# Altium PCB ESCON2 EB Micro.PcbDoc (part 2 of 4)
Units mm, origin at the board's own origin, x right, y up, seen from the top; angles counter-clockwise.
Board outline 75.6 x 72 mm, 8 copper layers (Top Side, Mid Layer 1, Mid Layer 2, Mid Layer 3, Mid Layer 4, Mid Layer 5, Mid Layer 6, Bottom Side), stack 1.555 mm thick; 192 components, 85 nets, 547 pads, 2387 vias.
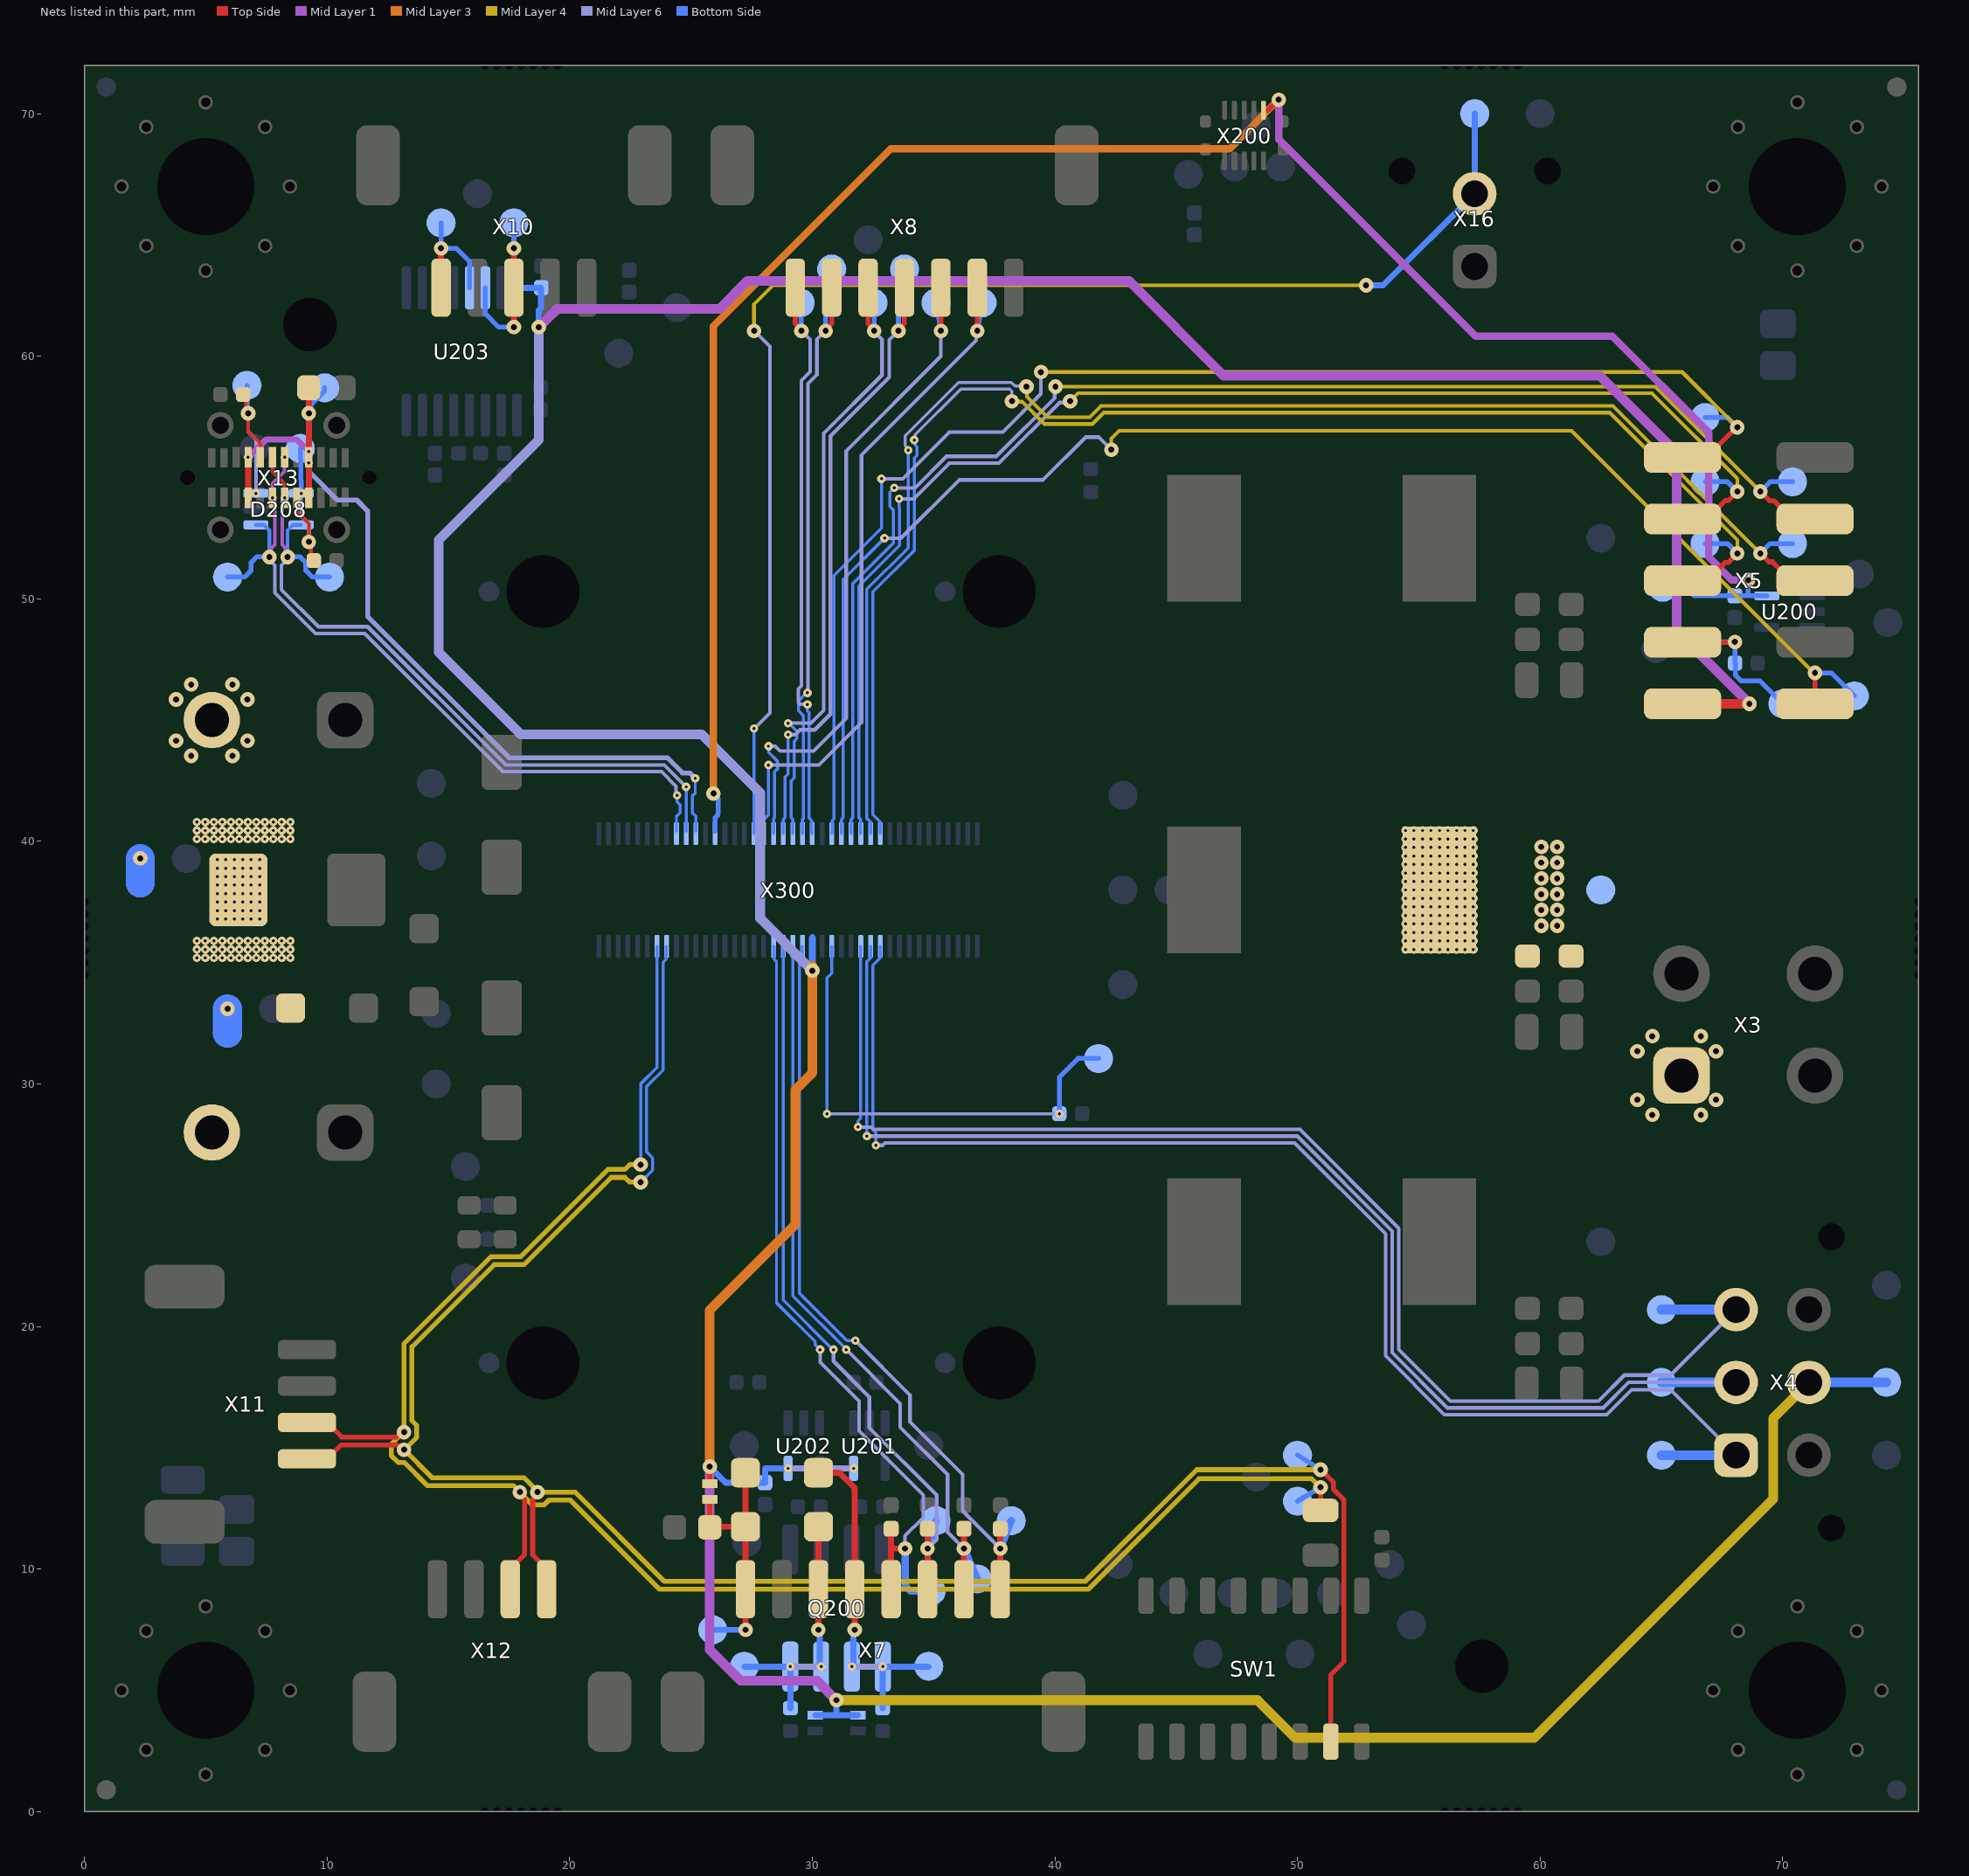
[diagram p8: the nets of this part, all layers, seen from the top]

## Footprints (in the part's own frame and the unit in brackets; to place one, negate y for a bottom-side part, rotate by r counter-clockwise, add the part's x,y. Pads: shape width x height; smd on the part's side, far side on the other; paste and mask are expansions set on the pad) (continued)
WURTH_9774040943_NPTH [mm] "WA-SMST SMT Steel Spacer with through hole Ø2.25mm, L=4mm"
  round 0 hole 3 unplated paste-2539.97 mask+1.25: 0(0,0)
  round 0.85 smd paste-5 mask+0.102: 1(2.225,0)
  Multi-Layer lines w0.85: 2.225,0 cw(c0,0) -2.225,0 cw(c0,0) 2.225,0
  body extent -2.17,-2.16 2.17,2.16, height 4

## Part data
C200 C201 C203 C207 C208 C209 C210 C211 C212: library part CMP-000709-3, "100nF X7R >=16V 20%", Case=0402, Case (Metric)=1005, Dielectric=X7R, Manufacturer=X, Max Operating Temperature=125°C, Maximum Working Voltage=16V, Min Operating Temperature=-55°C, Part Number="Ceramic, 0402, 100nF, 20%, >{}16V, X7R, @, Soft Termination: N, -55°C to 125°C", Tolerance=20%
C202 C206: library part CMP-000703-3, "100nF X7R >=100V 20%", Case=0603, Case (Metric)=1608, Dielectric=X7R, Manufacturer=X, Max Operating Temperature=125°C, Maximum Working Voltage=100V, Min Operating Temperature=-55°C, Part Number="Ceramic, 0603, 100nF, 20%, >{}100V, X7R, @, Soft Termination: N, -55°C to 125°C", Tolerance=20%
C204 C205: library part CMP-000937-4, "10nF X7R >=630V 20%", Case=0805, Case (Metric)=2012, Dielectric=X7R, Dielectric Withstanding Voltage="> 850V 1sec", Manufacturer=Murata, Max Operating Temperature=125°C, Maximum Working Voltage=630V, Min Operating Temperature=-55°C, Tolerance=20%
C300 C301 C302: library part CMP-000967-5, "Polymer Hybrid Elco 22uF >=80V 20% D=8mm, H=10.5mm", Case="G, D{}8mm, H{}10.5mm", Manufacturer=Panasonic, Max Operating Temperature=105°C, Maximum Working Voltage=80V, Min Operating Temperature=-55°C, Ripple Current=1.55A, Tolerance=20%
C303 C304 C305: library part CMP-001011-3, "470p C0G/NP0/X7R >=100V 20%", Case=0603, Case (Metric)=1608, Dielectric=C0G/NP0/X7R, Manufacturer=X, Max Operating Temperature=125°C, Maximum Working Voltage=100V, Min Operating Temperature=-55°C, Part Number="Ceramic, 0603, 470pF, 20%, >{}100V, C0G/NP0/X7R, @, Soft Termination: N, -55°C to 125°C", Tolerance=20%
C306 C307 C308: library part CMP-001012-4, "220pF C0G/NP0/X7R >=100V 20%", Case=0603, Case (Metric)=1608, Dielectric=C0G/NP0/X7R, Manufacturer=X, Max Operating Temperature=125°C, Maximum Working Voltage=100V, Min Operating Temperature=-55°C, Part Number="Ceramic, 0603, 220pF, 20%, >{}100V, C0G/NP0/X7R, @, Soft Termination: N, -55°C to 125°C", Tolerance=20%
D200: library part CMP-001106-5, "Transient Voltage Suppressor Diode, 12V V(RWM), Bidirectional, 100W, 1 Element, SOD-882/DFN1006", Breakdown Voltage=13V, Case="SOD-882; DFN1006", Manufacturer=Diodes, Max Operating Temperature=125°C, Min Operating Temperature=-40°C
D201 D204 D205: library part CMP-000606-13, "Diode Switching, >=70V, >=150mA, SOD882/DFN1006/0402/SOD-923F", Case="SOD882 / DFN1006 / 0402 / SOD-923F", Manufacturer=MCC, Max Operating Temperature=125°C, Min Operating Temperature=-40°C, Reverse Voltage=70V, RMS Current=150mA
D202 D203 D209 D210: library part CMP-000066-17, "Transient Voltage Suppressor Diode, 30V V(RWM), Bidirectional, ESD, 1 Element, 0402", Breakdown Voltage=30V, Case=0402, Manufacturer=Panasonic, Max Operating Temperature=125°C, Min Operating Temperature=-55°C
D206 D207 D300 D301: library part CMP-000633-9, "Schottky Diode, >=90V, >=1A, SOD-123FL/SOD-123W", Case="Sub SMA; SOD-123FL", Manufacturer="Taiwan Semiconductor", Max Operating Temperature=150°C, Min Operating Temperature=-55°C, Reverse Voltage=90V, RMS Current=1A
D208: library part CMP-000635-10, "Transient Voltage Suppressor Diode, 4-Line, 5V V(RWM), Unidirectional, 30W, 4 Element , SOT353/SC-88A", Breakdown Voltage=6.8V, Case="SOT353; SC-88A; SOT323-5L", Clamping Voltage=12V, Manufacturer=Nexperia, Max Breakdown Voltage=7.14V, Max Junction Temperature=150°C, Min Breakdown Voltage=6.46V, Min Operating Temperature=-65°C
D302 D303: library part CMP-001103-4, "Transient Voltage Suppressor Diode, 60V V(RWM), Unidirectional, 400W, 1 Element, DO-214AC", Breakdown Voltage=66.7V, Case=DO-214AC, Clamping Voltage=96.8V, Manufacturer=X, Max Operating Temperature=150°C, Min Operating Temperature=-55°C
DS200: library part CMP-000723-6, "Single Color Chip LED, red, 0603", Case=0603, Color(s)=Red, Manufacturer=Dialight, Max Operating Temperature=100°C, Min Operating Temperature=-40°C
DS201: library part CMP-000722-5, "Single Color Chip LED, green, 0603", Case=0603, Color(s)=Green, Manufacturer=Dialight, Max Operating Temperature=100°C, Min Operating Temperature=-40°C
F300: library part CMP-001757-3, "Electric Fuse, Very Fast Blow, 10A, 125VAC, 125VDC, 35A (IR), Clip Assembly", Case="0157 with Fuse Clip", Current Rating=10A, Manufacturer=Littelfuse, Max Operating Temperature=125°C, Maximum Working Voltage=125V, Min Operating Temperature=-55°C
FD200 FD201 FD202 FD203: library part CMP-000010-5, "Fiducial, Global, Round; 0.80 mm D, 1.60 mm Clearance"
L300 L301 L302: library part CMP-001747-7, "Inductor Shielded, 15uH, 20%, I_RMS>6.5A, I_Sat>9.8A, R<26mOhm, 12.0x12.0mm, Height<=10mm", Case=0, Max Operating Temperature=125°C, Min Operating Temperature=-40°C, RMS Current=5.7A, Saturation Current=9.8A, Tolerance=20%
LS200: library part CMP-001088-3, "Layer Stair 8 Layer"
MH200 MH201 MH202 MH203: library part CMP-001801-1, "Mounting Hole, Non-Plated; 9.00 mm Clearance, 4.00 mm Hole (with 8 vias), for 4mm Dia. Snap-In Spacer"
MH204 MH205: library part CMP-001004-5, "Mounting Hole, Non-Plated; 0.00 mm Clearance, 2.20 mm Hole"
MP200 MP201 MP202 MP203: library part CMP-001759-4, "WA-SNTI Plastic Spacer Stud, D=4.0mm, L=10mm, M3, SW=6", Max Operating Temperature=110°C, Min Operating Temperature=-30°C
MP300 MP301: library part CMP-001744-2, "WA-SMST SMT Steel Spacer with through hole Ø 2.25mm, L=4mm", Manufacturer=Wurth, Max Operating Temperature=150°C, Min Operating Temperature=-55°C
MP302 MP303: library part CMP-001745-2, "WA-SMST SMT Steel Spacer with internal Thread M2, L=4mm", Manufacturer=Wurth, Max Operating Temperature=150°C, Min Operating Temperature=-55°C
Q200: library part CMP-001108-5, "N-Channel MOSFET, Self Protected, 36V, 0.5ohm, SO-8", Case="SO-8, SOIC-8, PG-DSO-8", Drain Source Voltage=36V, Manufacturer="ST Microelectronics", Max Operating Temperature=150°C, Min Operating Temperature=-55°C
R200: library part CMP-000161-11, "47R 1% 62.5mW 100ppm", Case=0402, Case (Metric)=1050, Manufacturer=X, Max Junction Temperature=155°C, Maximum Overload Voltage=100V, Maximum Working Voltage=50V, Min Operating Temperature=-55°C, Part Number="Thick-Film, 0402, 47, 1%, 62.5mW@70°C, 50V, 100ppm, -55°C to 155°C", Power Rating=62.5mW, Power Rating Temperature=70°C, Temperature Coefficient=100ppm, Tolerance=1%
R202 R203: library part CMP-000197-11, "2.2k 1% 62.5mW 100ppm", Case=0402, Case (Metric)=1050, Manufacturer=X, Max Junction Temperature=155°C, Maximum Overload Voltage=100V, Maximum Working Voltage=50V, Min Operating Temperature=-55°C, Part Number="Thick-Film, 0402, 2.2k, 1%, 62.5mW@70°C, 50V, 100ppm, -55°C to 155°C", Power Rating=62.5mW, Power Rating Temperature=70°C, Temperature Coefficient=100ppm, Tolerance=1%
R204 R205: library part CMP-000173-11, "220R 1% 62.5mW 100ppm", Case=0402, Case (Metric)=1050, Manufacturer=X, Max Junction Temperature=155°C, Maximum Overload Voltage=100V, Maximum Working Voltage=50V, Min Operating Temperature=-55°C, Part Number="Thick-Film, 0402, 220, 1%, 62.5mW@70°C, 50V, 100ppm, -55°C to 155°C", Power Rating=62.5mW, Power Rating Temperature=70°C, Temperature Coefficient=100ppm, Tolerance=1%
R206: library part CMP-000935-4, "2M 5% 250mW 200ppm >=500V", Case=1206, Case (Metric)=3216, Manufacturer=X, Max Junction Temperature=155°C, Maximum Overload Voltage=1kV, Maximum Working Voltage=500V, Min Operating Temperature=-55°C, Part Number="Thick-Film, 1206, 2M, 5%, 250mW@70°C, 500V, 200ppm, -55°C to 155°C", Power Rating=250mW, Power Rating Temperature=70°C, Temperature Coefficient=200ppm, Tolerance=5%
R207 R208: library part CMP-000206-11, "5.1k 1% 62.5mW 100ppm", Case=0402, Case (Metric)=1050, Manufacturer=X, Max Junction Temperature=155°C, Maximum Overload Voltage=100V, Maximum Working Voltage=50V, Min Operating Temperature=-55°C, Part Number="Thick-Film, 0402, 5.1k, 1%, 62.5mW@70°C, 50V, 100ppm, -55°C to 155°C", Power Rating=62.5mW, Power Rating Temperature=70°C, Temperature Coefficient=100ppm, Tolerance=1%
R209: library part CMP-000325-10, "120R 1% 125mW 100ppm", Case=0805, Case (Metric)=2012, Manufacturer=X, Max Junction Temperature=155°C, Maximum Overload Voltage=300V, Maximum Working Voltage=150V, Min Operating Temperature=-55°C, Part Number="Thick-Film, 0805, 120, 1%, 125mW@70°C, 150V, 100ppm, -55°C to 155°C", Power Rating=125mW, Power Rating Temperature=70°C, Temperature Coefficient=100ppm, Tolerance=1%
R210: library part CMP-000466-10, "0R Jumper", Case=0402, Case (Metric)=1050, Manufacturer=X, Max Junction Temperature=155°C, Maximum Overload Voltage=100V, Maximum Working Voltage=50V, Min Operating Temperature=-55°C, Part Number="Thick-Film, 0402, 0, -55°C to 155°C", RMS Current=1A
R211 R212: library part CMP-000185-11, "680R 1% 62.5mW 100ppm", Case=0402, Case (Metric)=1050, Manufacturer=X, Max Junction Temperature=155°C, Maximum Overload Voltage=100V, Maximum Working Voltage=50V, Min Operating Temperature=-55°C, Part Number="Thick-Film, 0402, 680, 1%, 62.5mW@70°C, 50V, 100ppm, -55°C to 155°C", Power Rating=62.5mW, Power Rating Temperature=70°C, Temperature Coefficient=100ppm, Tolerance=1%
R213 R214 R215 R324: library part CMP-000492-11, "10k 1% 62.5mW 100ppm", Case=0402, Case (Metric)=1050, Manufacturer=X, Max Junction Temperature=155°C, Maximum Overload Voltage=100V, Maximum Working Voltage=50V, Min Operating Temperature=-55°C, Part Number="Thick-Film, 0402, 10k, 1%, 62.5mW@70°C, 50V, 100ppm, -55°C to 155°C", Power Rating=62.5mW, Power Rating Temperature=70°C, Temperature Coefficient=100ppm, Tolerance=1%
R309 R310 R311: library part CMP-001764-2, "270R 1% 250mW 100ppm", Case=0805, Case (Metric)=2012, Max Junction Temperature=155°C, Maximum Overload Voltage=300V, Maximum Working Voltage=150V, Min Operating Temperature=-55°C, Part Number="Thick-Film, 0805, 270, 1%, 250mW@70°C, 150V, 100ppm, -55°C to 155°C", Power Rating=250mW, Power Rating Temperature=70°C, Temperature Coefficient=100ppm, Tolerance=1%
STEG200 STEG201 STEG202 STEG203 STEG204 STEG205: library part CMP-000007-5, "Breakaway tabs; 4.00 mm L X 0.90 mm W, 7 Hole"
SW1: library part CMP-001031-3, "Slide Dip Switch, 8 Switches, 0.025A, 24VDC, SMD", Manufacturer=Diptronics, Max Operating Temperature=85°C, Min Operating Temperature=-40°C
SYM200: library part CMP-001233-2, "Barcode EMS; 5.0 x 5.0 mm"
SYM201 SYM202: library part CMP-000018-5, "ESD-Sign; 5.0 mm L X 4.5 mm W"
SYM203: library part CMP-001854-7, "PCB Marking; 12.0 x 6.0 mm"
TP200 TP201 TP202 TP203 TP204 TP205 TP206 TP207 TP208 TP209 TP211 TP212 TP213 TP214 TP215 TP216 TP217 TP218 TP219 TP220 TP221 TP222 TP223 TP224 TP225 TP226 TP227 TP228 TP229 TP230 TP231 TP232 TP233 TP234 TP235 TP236 TP237 TP238 TP239 TP240 TP241 TP242 TP243 TP244 TP245 TP246 TP247 TP248 TP249 TP250 TP251 TP252 TP253 TP254 TP255 TP256 TP257 TP258 TP259 TP260 TP261 TP262 TP263 TP264 TP265 TP266 TP267 TP268 TP269 TP270 TP271 TP272 TP300 TP301 TP302 TP304 TP309 TP313 TP314 TP315 TP316: library part CMP-000014-7, "Test Point; 1 pin, 1.20 mm D"
U200: library part CMP-001041-6, "Single buffer with Schmitt-Trigger inputs", Case="5-TSSOP, SC-70-5, SOT-353", Manufacturer="Texas Instruments", Max Operating Temperature=125°C, Max Storage Temperature=150°C, Max Supply Voltage=5.5V, Min Operating Temperature=-40°C, Min Storage Temperature=-65°C, Min Supply Voltage=1.65V
U201 U202: library part CMP-002037-1, "Single, 2-Input NAND Gate, 5V", Case="SC-88A , SC-70-5, SOT353-1", Max Operating Temperature=125°C, Max Supply Voltage=5.5V, Min Operating Temperature=-40°C, Min Supply Voltage=4.5V
U203: library part CMP-000646-4, "RS-232 Line Transceiver, Dual channel 120kbps , 5.0V, TSSOP16", Case=TSSOP16, Manufacturer="Texas instruments", Max Operating Temperature=85°C, Max Supply Voltage=5.5V, Min Operating Temperature=-40°C, Min Supply Voltage=4.5V
X1 X2: library part CMP-001018-6, "Mini-Fit Jr. Vertical Header, 4.20mm Pitch, Dual Row, 2 Circuits, without Snap-in Plastic Peg PCB Lock, Tin, Natural", Max Operating Temperature=105°C, Min Operating Temperature=-40°C, Operating Current=9A, Operating Voltage=600V
X3: library part CMP-001016-8, "Mini-Fit Jr. Vertical Header, 4.20mm Pitch, Dual Row, 4 Circuits, without Snap-in Plastic Peg PCB Lock, Tin, Natural", Max Operating Temperature=105°C, Min Operating Temperature=-40°C, Operating Current=9A, Operating Voltage=600V
X4: library part CMP-001098-6, "Micro-Fit 3.0 Vertical Header, 3.00mm Pitch, Dual Row, 6 Circuits, with PCB Polarizing Peg, Black", Manufacturer=Molex, Max Operating Temperature=105°C, Min Operating Temperature=-40°C, Operating Current=8.5A, Operating Voltage=600V
X5: library part CMP-001165-3, "Header, 2.54mm Pitch, Dual Row, SMT, Vertical, 10 Circuits", Manufacturer=Amphenol, Max Operating Temperature=125°C, Min Operating Temperature=-65°C, Operating Current=3A, Operating Voltage=500V
X7: library part CMP-001014-7, "1.50mm Pitch, CLIK-Mate PCB Receptacle, Single Row, Surface Mount, Tin Plating, Positive Lock, with Pick-and-Place Polyimide Tape, 8 Circuits, Beige", Manufacturer=Molex, Max Operating Temperature=105°C, Min Operating Temperature=-40°C, Operating Current=2A, Operating Voltage=100V
X8: library part CMP-001015-7, "1.50mm Pitch, CLIK-Mate PCB Receptacle, Single Row, Surface Mount, Tin Plating, Positive Lock, with Pick-and-Place Polyimide Tape, 7 Circuits, Beige", Manufacturer=Molex, Max Operating Temperature=105°C, Min Operating Temperature=-40°C, Operating Current=2A, Operating Voltage=100V
X10: library part CMP-001023-6, "1.50mm Pitch, CLIK-Mate PCB Receptacle, Single Row, Surface Mount, Tin Plating, Positive Lock, with Pick-and-Place Polyimide Tape, 5 Circuits, Beige", Manufacturer=Molex, Max Operating Temperature=105°C, Min Operating Temperature=-40°C, Operating Current=2A, Operating Voltage=100V
X11 X12: library part CMP-001170-6, "1.50mm Pitch, CLIK-Mate PCB Receptacle, Single Row, Surface Mount, Tin Plating, Positive Lock, with Pick-and-Place Polyimide Tape, 4 Circuits, Beige", Manufacturer=Molex, Max Operating Temperature=105°C, Min Operating Temperature=-40°C, Operating Current=2A, Operating Voltage=100V
X13: library part CMP-001110-9, "USB Type C, SHLD, 24poles, vertical", Manufacturer=GTC, Max Operating Temperature=85°C, Min Operating Temperature=-25°C
X16: library part CMP-001107-4, "Micro-Fit 3.0 Vertical Header, 3.00mm Pitch, Dual Row, 2 Circuits, with PCB Polarizing Peg, Black", Manufacturer=Molex, Max Operating Temperature=105°C, Min Operating Temperature=-40°C, Operating Current=8.5A, Operating Voltage=600V
X200: library part CMP-001083-11, "Board to Board Connector, 2*5 pole, SMD, 0.4mm pitch, 1.5mm stacking Height", Manufacturer=Panasonic, Max Operating Temperature=85°C, Min Operating Temperature=-55°C, Operating Current=300mA, Operating Voltage=60V
X300: library part CMP-001746-7, "SS4 0.40 mm Micro Blade & Beam Ultra Fine Pitch Socket, 80 poles", Manufacturer=Samtec, Max Operating Temperature=125°C, Min Operating Temperature=-55°C, Operating Current=1.6A, Operating Voltage=155V

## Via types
v1: diameter 0.35, hole 0.125, Top Side to Mid Layer 1, tented both sides, 1630 vias
v2: diameter 0.6, hole 0.25, Top Side to Bottom Side, 412 vias
v3: diameter 0.35, hole 0.125, Mid Layer 6 to Bottom Side, tented both sides, 345 vias

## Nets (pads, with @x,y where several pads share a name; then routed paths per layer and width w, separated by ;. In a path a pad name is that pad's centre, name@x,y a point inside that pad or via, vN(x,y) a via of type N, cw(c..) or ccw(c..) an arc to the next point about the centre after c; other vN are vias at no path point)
3V3: C200.2 TP202.1 U200.5 X200.1 X300.56 | length 85.5
  Top Side w0.2: X200.1@48.6,70.145 48.795,70.145 v2(49.225,70.575)
  Mid Layer 1 w0.3: v2(49.225,70.575) 49.225,68.95 57.35,60.825 62.975,60.825 66.95,56.85 66.95,51.725 67.9,50.775 v2(68.575,50.775)
  Mid Layer 3 w0.3: v2(25.925,41.975) 25.925,61.25 33.225,68.55 47.2,68.55 v2(49.225,70.575)
  Bottom Side w0.2: v2(25.925,41.975) 26.125,41.775 26.125,41.15 26.1,41.125 26.1,41.075 26,40.975 X300.56@26,40.425 ; TP202.1@65.05,50.475 66,50.475 66.35,50.125 C200.2@68.025,50.125 68.568,50.125 ; v2(68.575,50.775) 68.575,50.132 68.568,50.125 ; U200.5@69.34,50.125 68.568,50.125
5V0_sensor1_2: C201.2 C207.1 D201.2 D204.2 D205.2 TP223.1 U201.5 U202.5 U203.16 X4.5 X5.2 X300.35 | length 205.9
  Top Side w0.25: D201.2@25.775,13.525 v2(25.775,14.225)
  Top Side w0.4: X5.2@65.87,45.67 68.62,45.67 v2(68.625,45.675)
  Mid Layer 1 w0.4: v2(18.725,61.2) 19.475,61.95 26.175,61.95 27.325,63.1 43.05,63.1 46.95,59.2 62.45,59.2 65.625,56.025 65.625,48.675 v2(68.625,45.675) ; v2(25.775,14.225) 25.775,6.675 27.05,5.4 30.2,5.4 v2(31,4.6)
  Mid Layer 3 w0.4: v2(25.775,14.225) 25.775,20.675 29.3,24.2 29.3,29.75 30,30.45 v2(30,34.675) v2@30,34.875
  Mid Layer 6 w0.25: v3(29,14.155) v3(31.7,14.155)
  Mid Layer 6 w0.4: v2(18.725,61.2) 18.725,56.55 14.6,52.425 14.6,47.8 17.99,44.41 25.44,44.41 27.85,42 27.85,36.825 v2(30,34.675)
  Mid Layer 4 w0.4: v2(31,4.6) 48.35,4.6 49.9,3.05 59.75,3.05 69.6,12.9 69.6,16.225 X4.5@71.075,17.7
  Bottom Side w0.25: U203.16@17.825,62.825 C207.1@18.825,62.825 18.825,62 18.725,61.9 v2(18.725,61.2) ; v2(25.775,14.225) 26.435,13.565 C201.2@28.05,13.565 28.05,14.155 v3(29,14.155) ; D205.2@30.125,3.975 31,3.975 ; v2@31,4.75 v2(31,4.6) 31,3.975 ; D204.2@31.875,3.975 31,3.975
  Bottom Side w0.3: v2(30,34.675) X300.35@30,35.675 X300.35@30,36.025
  Bottom Side w0.4: X4.5@71.075,17.7 TP223.1@74.275,17.7
ADC_CB_Ident: R324.2 TP309.1 X300.31 | length 20
  Mid Layer 6 w0.125: v3(30.6,28.775) v3(40.18,28.775)
  Bottom Side w0.125: v3(30.6,28.775) 30.6,34.375 30.8,34.575 X300.31@30.8,35.675
  Bottom Side w0.2: v3(40.18,28.775) 40.18,30.28 40.95,31.05 TP309.1@41.8,31.05
C_AnIN1+: TP230.1 X8.1 X300.36 | length 24.5
  Top Side w0.2: X8.1@29.3,62.825 29.3,61.352 29.55,61.102 v2(29.55,61.05)
  Mid Layer 6 w0.15: v2(29.55,61.05) 29.91,60.69 29.91,59.356 29.55,58.996 29.55,46.405 29.425,46.28 29.425,45.738 29.513,45.65 v3(29.8,45.65)
  Bottom Side w0.125: v3(29.8,45.65) 29.8,45.379 29.875,45.304 29.875,40.961 29.975,40.861 29.975,40.35 X300.36@30,40.325
  Bottom Side w0.2: TP230.1@29.5,62.2 29.55,62.15 v2(29.55,61.05)
C_AnIN1-: TP231.1 X8.2 X300.38 | length 25.8
  Top Side w0.2: v2@30.55,61.102 30.8,61.352 X8.2@30.8,62.825
  Mid Layer 6 w0.15: v3(29.8,46.125) 29.825,46.15 29.825,58.875 30.189,59.239 30.189,60.689 v2(30.55,61.05)
  Bottom Side w0.125: X300.38@29.6,40.325 29.6,40.925 29.625,40.95 29.625,45.2 29.438,45.388 29.438,45.8 29.762,46.125 v3(29.8,46.125)
  Bottom Side w0.2: v2(30.55,61.05) 30.55,62 30.8,62.25 TP231.1@30.8,63.6
C_AnIN2+: TP232.1 X8.3 X300.40 | length 26.4
  Top Side w0.2: X8.3@32.3,62.825 32.3,61.352 32.55,61.102 v2(32.55,61.05)
  Mid Layer 6 w0.15: v3(29,44.875) 29.95,44.875 30.475,45.4 30.475,56.825 32.875,59.225 32.875,60.687 32.55,61.012 v2(32.55,61.05)
  Bottom Side w0.125: v3(29,44.875) 29.038,44.875 29.363,44.55 29.363,44.238 29.25,44.125 29.25,42.625 29.125,42.5 29.125,40.975 29.2,40.9 X300.40@29.2,40.325
  Bottom Side w0.2: TP232.1@32.5,62.2 32.55,62.15 v2(32.55,61.05)
C_AnIN2-: TP233.1 X8.4 X300.42 | length 27.7
  Top Side w0.2: v2@33.55,61.102 33.8,61.352 X8.4@33.8,62.825
  Mid Layer 6 w0.15: v3(29,44.4) 29.3,44.4 29.5,44.6 30.1,44.6 30.75,45.25 30.75,56.711 33.175,59.136 33.175,60.675 v2(33.55,61.05)
  Bottom Side w0.125: X300.42@28.8,40.325 28.8,40.9 28.875,40.975 28.875,42.65 29,42.775 v3(29,44.4)
  Bottom Side w0.2: v2(33.55,61.05) 33.55,62 33.8,62.25 TP233.1@33.8,63.6
C_AnOUT1: TP234.1 X8.5 X300.44 | length 28.2
  Top Side w0.2: v2(35.3,61.05) X8.5@35.3,62.825
  Mid Layer 6 w0.15: v3(28.2,43.925) 28.475,43.925 28.675,43.725 30.05,43.725 31.4,45.075 31.4,56.1 35.3,60 v2(35.3,61.05)
  Bottom Side w0.125: v3(28.2,43.925) 28.206,43.919 28.206,43.669 28.563,43.313 28.563,42.988 28.45,42.875 28.45,40.975 28.4,40.925 X300.44@28.4,40.325
  Bottom Side w0.2: TP234.1@35.1,62.2 v2(35.3,61.05)
C_AnOUT2: TP237.1 X8.6 X300.46 | length 28.5
  Top Side w0.2: v2(36.8,61.05) X8.6@36.8,62.825
  Mid Layer 6 w0.15: v3(28.2,43.15) 30.275,43.15 32.025,44.9 32.025,55.925 36.754,60.654 36.754,61.004 v2(36.8,61.05)
  Bottom Side w0.125: X300.46@28,40.325 28,40.9 28.2,41.1 v3(28.2,43.15)
  Bottom Side w0.2: v2(36.8,61.05) TP237.1@37,62.2
C_CANH: SW1.7 TP240.1 X11.1 X12.1 X300.65 | length 90.9
  Top Side w0.2: X11.1@9.175,14.55 10.015,14.55 10.59,15.125 12.867,15.125 13.067,14.925 v2(13.175,14.925) ; v2(18.675,13.175) 18.675,13.067 18.475,12.867 18.475,10.59 19.05,10.015 X12.1@19.05,9.175 ; v2(50.95,14.1) 50.967,14.1 51.475,13.592 51.475,13.3 51.917,12.858 51.917,6.192 51.375,5.65 SW1.7@51.375,2.893
  Mid Layer 4 w0.2: v2@22.937,25.962 22.463,25.962 22.275,26.15 21.71,26.15 18.11,22.55 16.885,22.55 13.5,19.165 13.5,16.125 13.7,15.925 13.7,15.433 13.192,14.925 v2(13.175,14.925) 14.325,13.775 18.111,13.775 18.675,13.211 v2(18.675,13.175) 20.225,13.175 23.9,9.5 41.25,9.5 45.85,14.1 v2(50.95,14.1)
  Bottom Side w0.125: v2(22.925,25.95) 23.425,26.45 23.425,26.955 23.175,27.205 23.175,29.9 23.85,30.575 23.85,35.014 23.975,35.139 23.975,35.65 X300.65@24,35.675
  Bottom Side w0.2: TP240.1@50,14.7 v2(50.95,14.1)
C_CANL: R209.2 TP241.1 X11.2 X12.2 X300.67 | length 80.4
  Top Side w0.2: X11.2@9.175,16.025 10.025,16.025 10.6,15.45 12.867,15.45 13.067,15.65 v2(13.175,15.65) ; X12.2@17.575,9.175 17.575,10.025 18.15,10.6 18.15,12.867 17.95,13.067 v2(17.95,13.175) ; R209.2@50.95,12.425 v2(50.95,13.375)
  Mid Layer 4 w0.2: v2(22.925,26.675) 22.475,26.675 22.275,26.475 21.575,26.475 17.975,22.875 16.75,22.875 13.175,19.3 v2(13.175,15.65) 13.146,15.65 12.643,15.147 12.643,14.686 12.93,14.4 13.175,14.4 14.125,13.45 17.675,13.45 v2(17.95,13.175) 17.95,13.158 18.458,12.65 18.95,12.65 19.15,12.85 20.025,12.85 23.7,9.175 41.385,9.175 45.935,13.725 50.583,13.725 50.933,13.375 v2(50.95,13.375)
  Bottom Side w0.125: v2(22.925,26.675) 22.925,30.004 23.6,30.679 X300.67@23.6,35.675
  Bottom Side w0.2: TP241.1@50,12.8 v2(50.95,13.375)
C_DigIN1: D203.2 TP269.1 X7.1 X300.37 | length 32.2
  Top Side w0.25: X7.1@37.75,9.175 D203.2@37.75,11.665
  Mid Layer 6 w0.15: v3(31.775,19.425) 34.025,17.175 34.025,16.075 36.2,13.9 36.2,12.4 v2(37.75,10.85)
  Bottom Side w0.125: X300.37@29.6,35.675 29.575,35.65 29.575,35.139 29.475,35.039 29.475,21.375 31.425,19.425 v3(31.775,19.425)
  Bottom Side w0.3: v2(37.75,10.85) TP269.1@38.2,12
C_DigIN2: D202.2 TP270.1 X7.2 X300.39 | length 31.6
  Top Side w0.25: X7.2@36.25,9.175 D202.2@36.25,11.665
  Mid Layer 6 w0.15: v3(31.4,19.05) 33.625,16.825 33.625,15.85 35.575,13.9 35.575,11.525 v2(36.25,10.85)
  Bottom Side w0.125: X300.39@29.2,35.675 29.2,21.261 v3@31.406,19.056
  Bottom Side w0.3: v2(36.25,10.85) TP270.1@36.8,9.6
C_DigIN3: D210.2 TP271.1 X7.3 X300.41 | length 31.3
  Top Side w0.25: X7.3@34.75,9.175 v2(34.75,10.85) D210.2@34.75,11.665
  Mid Layer 6 w0.15: v3(30.875,19.05) 30.875,18.575 32.35,17.1 32.35,15.825 35.125,13.05 35.125,11.225 v2(34.75,10.85)
  Bottom Side w0.125: X300.41@28.8,35.675 28.8,21.095 v3@30.86,19.035
  Bottom Side w0.3: v2(34.75,10.85) TP271.1@35.1,12
C_DigIN4: D209.2 TP272.1 X7.4 X300.43 | length 33.5
  Top Side w0.25: X7.4@33.25,9.175 33.25,10.85 ; D209.2@33.25,11.665 33.25,10.85 ; v2(33.825,10.85) 33.25,10.85
  Mid Layer 6 w0.15: v3(30.325,19.05) 30.325,18.525 31.925,16.925 31.925,15.7 34.575,13.05 34.575,12.125 33.825,11.375 v2(33.825,10.85)
  Bottom Side w0.125: X300.43@28.4,35.675 28.425,35.65 28.425,35.139 28.525,35.039 28.525,20.982 30.125,19.382 30.125,19.25 v3(30.325,19.05)
  Bottom Side w0.3: v2(33.825,10.85) 33.825,9.325 34.05,9.1 TP272.1@34.9,9.1
C_DigOUT1: D206.2 Q200.5 Q200.6 R202.1 TP224.1 X7.5 | length 14
  Top Side w0.25: D206.2@30.255,13.975 31.125,13.975 31.75,13.35 X7.5@31.75,9.175 v2(31.75,7.5)
  Mid Layer 6 w0.25: v3(31.635,5.98) v3(32.905,5.98)
  Bottom Side w0.25: v3(31.635,5.98) 31.693,6.038 31.693,7.443 v2(31.75,7.5) ; R202.1@32.9,4.27 Q200.5@32.9,5.98 ; v3(32.905,5.98) TP224.1@34.8,5.98
C_DigOUT2: D207.2 Q200.7 Q200.8 R203.1 TP225.1 X7.6 | length 10.7
  Top Side w0.25: v2(30.25,7.5) X7.6@30.25,9.175 ; X7.6@30.255,9.175 D207.2@30.255,11.75
  Mid Layer 6 w0.25: v3(29.095,5.98) v3(30.365,5.98)
  Bottom Side w0.25: TP225.1@27.2,5.98 v3(29.095,5.98) ; R203.1@29.1,4.27 Q200.8@29.1,5.975 ; v2(30.25,7.5) 30.308,7.443 30.308,6.038 v3(30.365,5.98)
C_MotorTemp: TP260.1 X16.2 X300.48 | length 57.2
  Mid Layer 6 w0.15: v3(27.6,44.65) 28.25,45.3 28.25,60.4 v2(27.6,61.05)
  Mid Layer 4 w0.15: v2(27.6,61.05) 27.6,62.15 28.375,62.925 v2(52.825,62.925)
  Bottom Side w0.125: X300.48@27.6,40.325 v3(27.6,44.65)
  Bottom Side w0.25: v2(52.825,62.925) 53.525,62.925 X16.2@57.3,66.7 TP260.1@57.3,70
C_S1_Hall1: TP266.1 X4.1 X300.21 | length 56.1
  Mid Layer 6 w0.15: v3(32.625,27.475) 32.9,27.475 33,27.575 49.875,27.575 53.625,23.825 53.625,18.8 56.05,16.375 62.75,16.375 63.775,17.4 65.375,17.4 X4.1@68.075,14.7
  Bottom Side w0.125: v3(32.625,27.475) 32.625,28 32.5,28.125 32.5,34.9 32.8,35.2 X300.21@32.8,35.675
  Bottom Side w0.4: TP266.1@65,14.7 X4.1@68.075,14.7
C_S1_Hall2: TP267.1 X4.2 X300.23 | length 54.8
  Mid Layer 6 w0.15: v3(32.25,27.85) 49.989,27.85 53.9,23.939 53.9,18.925 56.175,16.65 62.6,16.65 63.65,17.7 X4.2@68.075,17.7
  Bottom Side w0.125: v3(32.25,27.85) 32.25,35.047 32.4,35.197 X300.23@32.4,35.675
  Bottom Side w0.4: TP267.1@65,17.7 X4.2@68.075,17.7
C_S1_Hall3: TP268.1 X4.3 X300.25 | length 55.9
  Mid Layer 6 w0.15: v3(31.888,28.225) 32.425,28.225 32.525,28.125 50.103,28.125 54.175,24.053 54.175,19.05 56.3,16.925 62.4,16.925 63.475,18 65.375,18 X4.3@68.075,20.7
  Bottom Side w0.125: v3(31.888,28.225) 31.888,28.488 32,28.6 X300.25@32,35.675
  Bottom Side w0.4: TP268.1@65,20.7 X4.3@68.075,20.7
C_S2_/A: TP216.1 X5.5 X300.24 | length 61.1
  Top Side w0.2: v2(69.075,51.875) 69.425,51.525 69.575,51.525 70.35,50.75 X5.5@71.33,50.75
  Mid Layer 6 w0.125: v3(33.95,56.125) 33.95,56.186 33.828,56.308 33.828,56.721 36.032,58.925 38.211,58.925 38.359,58.777 38.798,58.777 v2(38.825,58.75)
  Mid Layer 4 w0.15: v2(38.825,58.75) 38.846,58.729 38.846,58.329 39.684,57.491 41.441,57.491 41.9,57.95 63,57.95 v2(69.075,51.875)
  Bottom Side w0.125: X300.24@32.4,40.325 32.4,40.803 32.25,40.953 32.25,50.396 33.95,52.096 v3(33.95,56.125)
  Bottom Side w0.2: v2(69.075,51.875) 69.475,52.275 TP216.1@70.4,52.275
C_S2_/B: TP218.1 X5.7 X300.28 | length 58.8
  Top Side w0.2: v2(69.075,54.425) 69.458,54.042 69.633,54.042 70.385,53.29 X5.7@71.33,53.29
  Mid Layer 6 w0.15: v3(33.375,54.575) 34.236,54.575 35.536,55.875 37.581,55.875 39.99,58.284 39.99,58.715 v2(40.025,58.75)
  Mid Layer 4 w0.15: v2(40.025,58.75) 64.75,58.75 v2(69.075,54.425)
  Bottom Side w0.125: X300.28@31.6,40.325 31.6,40.9 31.675,40.975 31.675,50.634 33.35,52.309 33.35,53.65 33.2,53.8 33.2,54.4 v3(33.375,54.575)
  Bottom Side w0.2: v2(69.075,54.425) 69.475,54.825 TP218.1@70.4,54.825
C_S2_A_HsDgin1: TP217.1 X5.6 X300.22 | length 60
  Top Side w0.2: X5.6@65.87,50.75 66.875,50.75 67.625,51.5 67.75,51.5 v2(68.125,51.875)
  Mid Layer 6 w0.125: v3(34.2,56.55) 34.241,56.591 34.241,56.772 36.125,58.656 38.126,58.656 38.218,58.564 38.218,58.157 v2(38.225,58.15)
  Mid Layer 4 w0.15: v2(38.225,58.15) 38.246,58.129 38.646,58.129 39.568,57.207 41.546,57.207 42.014,57.675 62.87,57.675 68.125,52.42 v2(68.125,51.875)
  Bottom Side w0.125: X300.22@32.8,40.325 32.8,40.8 32.5,41.1 32.5,50.293 34.2,51.993 34.2,55.8 34.313,55.913 34.313,56.275 34.243,56.345 34.243,56.507 v3(34.2,56.55)
  Bottom Side w0.2: TP217.1@66.8,52.275 67.725,52.275 v2(68.125,51.875)
C_S2_B_HsDgin2: TP219.1 X5.8 X300.26 | length 57.1
  Top Side w0.2: X5.8@65.87,53.29 66.865,53.29 67.625,54.05 67.75,54.05 v2(68.125,54.425)
  Mid Layer 6 w0.15: v3(33.575,54.125) 34.175,54.125 35.65,55.6 37.696,55.6 40.185,58.089 40.564,58.089 v2(40.625,58.15)
  Mid Layer 4 w0.15: v2(40.625,58.15) 40.95,58.475 64.606,58.475 68.125,54.956 v2(68.125,54.425)
  Bottom Side w0.125: X300.26@32,40.325 32,40.9 31.925,40.975 31.925,50.531 33.6,52.206 33.6,53.754 33.575,53.779 v3(33.575,54.125)
  Bottom Side w0.2: TP219.1@66.8,54.825 67.725,54.825 v2(68.125,54.425)
C_S2_Clock_HsDgout1: D200.2 R200.2 TP215.1 X5.4 | length 7
  Top Side w0.2: X5.4@65.87,48.21 68.01,48.21 v2(68.025,48.225)
  Bottom Side w0.2: D200.2@67.025,48.225 v2(68.025,48.225) 68.025,47.355 68.043,47.337 68.043,46.857 68.288,46.612 69.063,46.612 TP215.1@70,45.675
C_S2_Data_HsDgin4: TP213.1 X5.1 X300.30 | length 61.2
  Top Side w0.2: v2(71.325,46.95) 71.33,46.945 X5.1@71.33,45.67
  Mid Layer 6 w0.15: v3(32.975,52.5) 33.65,52.5 36.05,54.9 39.5,54.9 41.266,56.666 41.809,56.666 v2(42.325,56.15)
  Mid Layer 4 w0.15: v2(42.325,56.15) 42.325,56.6 42.65,56.925 61.295,56.925 71.27,46.95 v2(71.325,46.95)
  Bottom Side w0.125: X300.30@31.2,40.325 31.2,40.9 31.275,40.975 31.275,50.8 v3(32.975,52.5)
  Bottom Side w0.2: v2(71.325,46.95) 72,46.95 TP213.1@72.95,46
C_S2_I_HsDgin3: TP220.1 X5.10 X300.32 | length 58.3
  Top Side w0.2: X5.10@65.87,55.83 66.855,55.83 68.1,57.075 v2(68.125,57.075)
  Mid Layer 6 w0.15: v3(32.85,54.95) 33.725,54.95 35.65,56.875 37.85,56.875 39.425,58.45 v2(39.425,59.35)
  Mid Layer 4 w0.15: v2(39.425,59.35) 65.85,59.35 v2(68.125,57.075)
  Bottom Side w0.125: X300.32@30.8,40.325 30.825,40.35 30.825,40.861 30.888,40.923 30.888,50.961 32.85,52.923 v3(32.85,54.95)
  Bottom Side w0.2: TP220.1@66.8,57.475 67.725,57.475 v2(68.125,57.075)
C_UART_RxD: TP262.1 U203.13 X10.1 | length 5.2
  Top Side w0.25: X10.1@14.7,62.825 v2@14.7,64.45
  Bottom Side w0.2: TP262.1@14.7,65.5 14.7,64.451 15.325,64.45 15.875,63.9 U203.13@15.875,62.825
  other v2: 14.7,64.45
C_UART_TxD: TP263.1 U203.14 X10.3 | length 6.8
  Top Side w0.25: v2(17.7,61.2) X10.3@17.7,62.825 v2(17.7,64.45)
  Bottom Side w0.2: U203.14@16.525,62.825 16.525,61.75 17.075,61.2 v2@17.7,61.2 ; v2(17.7,64.45) TP263.1@17.7,65.5
C_USB_CC1: D208.3 R207.1 TP249.1 X13.A5 | length 7.5
  Top Side w0.15: R207.1@6.545,58.425 6.664,58.306 6.664,57.736 v2(6.75,57.65) 6.75,56.9 7.25,56.4 X13.A5@7.25,55.835
  Mid Layer 6 w0.15: v2(6.75,57.65) 6.75,56.9 7.075,56.575 v3@7.075,54.35
  Bottom Side w0.2: TP249.1@6.7,58.8 6.7,57.771 ccw(c6.871,57.771) v2(6.75,57.65)
  other v3: 7.065,54.35
C_USB_CC2: D208.4 R208.1 TP254.1 X13.B5 | length 6.9
  Top Side w0.15: X13.B5@8.75,54.165 8.75,53.6 9.25,53.1 v2(9.25,52.35) 9.336,52.264 9.336,51.694 R208.1@9.455,51.575
  Mid Layer 6 w0.15: v3(8.935,54.35) 8.925,54.34 8.925,53.425 9.25,53.1 v2(9.25,52.35)
  Bottom Side w0.15: D208.4@8.933,54.444 v3(8.935,54.35)
  Bottom Side w0.2: TP254.1@8.9,56.2 D208.4@8.933,54.444
C_USB_D+: D208.5 TP251.1 X13.A6 X13.B6 X300.62 | length 31.8
  Top Side w0.15: X13.A6@7.75,55.835 7.75,55.25 8.25,54.75 v1(8.25,54.165)
  Mid Layer 1 w0.15: v1(8.25,54.165) 8.25,54.111 8.15,54.011 8.15,52.225 8.291,52.084 8.291,51.809 v2(8.375,51.725)
  Mid Layer 6 w0.15: v2(8.375,51.725) 8.375,51.637 8.125,51.387 8.125,50.38 9.655,48.85 11.675,48.85 17.375,43.15 23.9,43.15 v3(24.8,42.25)
  Bottom Side w0.125: X300.62@24.8,40.425 v3(24.8,42.25)
  Bottom Side w0.15: v2(8.375,51.725) 8.375,52.817 8.608,53.05 D208.5@8.935,53.05
  Bottom Side w0.2: v2(8.375,51.725) 8.9,51.725 9.125,51.5 9.125,51.175 9.4,50.9 TP251.1@10.1,50.9
C_USB_D-: D208.1 TP252.1 X13.A7 X13.B7 X300.64 | length 31.8
  Mid Layer 1 w0.15: v2(7.625,51.725) 7.709,51.809 7.709,52.084 7.85,52.225 7.85,54.011 7.75,54.111 v1(7.75,54.165) 7.75,54.75 8.25,55.25 v1(8.25,55.835)
  Mid Layer 6 w0.15: v2(7.625,51.725) 7.625,51.603 7.847,51.382 7.847,50.253 9.525,48.575 11.55,48.575 17.25,42.875 23.786,42.875 24.387,42.274 24.387,41.938 v3(24.425,41.9)
  Bottom Side w0.125: X300.64@24.4,40.425 24.4,41.036 24.55,41.186 24.55,41.5 24.425,41.625 v3(24.425,41.9)
  Bottom Side w0.15: D208.1@7.065,53.05 7.392,53.05 7.625,52.817 v2(7.625,51.725)
  Bottom Side w0.2: TP252.1@5.9,50.9 6.6,50.9 6.875,51.175 6.875,51.5 7.1,51.725 v2(7.625,51.725)
C_USB_VBUS: C206.2 TP247.1 X13.A4 X13.A9 X13.B4 X13.B9 X300.60 | length 38.8
  Top Side w0.25: X13.B9@6.75,54.225 v1(6.75,55.835) ; X13.B4@9.25,54.225 v1(9.25,55.6) ; v1(9.25,56.075) v2(9.25,57.65) 9.25,58.43 C206.2@9.25,58.7
  Mid Layer 1 w0.25: v1(6.75,55.835) 7.49,56.575 8.75,56.575 v1(9.25,56.075) v1(9.25,55.6)
  Mid Layer 6 w0.2: v2(9.25,57.65) 9.25,55.25 10.425,54.075 11.225,54.075 11.675,53.625 11.675,52.95 11.675,49.275 17.5,43.45 24.025,43.45 24.65,42.825 24.95,42.825 v3(25.175,42.6)
  Bottom Side w0.125: v3(25.175,42.6) 25.175,41.996 25.05,41.871 25.05,41.186 25.2,41.036 X300.60@25.2,40.425
  Bottom Side w0.2: v2(9.25,57.65) 9.327,57.727 9.327,58.001 9.9,58.574 TP247.1@9.9,58.7
C_VDigIO: C202.2 D201.1 D206.1 D207.1 TP229.1 X7.8 | length 10.5
  Top Side w0.25: D201.1@25.775,12.875 C202.2@25.775,11.725 25.8,11.75 D207.1@27.245,11.75 ; X7.8@27.245,9.175 D207.1@27.245,11.75 ; D206.1@27.245,13.975 D207.1@27.245,11.75 ; v2(27.25,7.5) X7.8@27.25,9.175
  Bottom Side w0.25: TP229.1@25.9,7.5 v2(27.25,7.5)
C_VL: D300.2 TP205.1 X2.2 | length 1
  Bottom Side w1.2: TP205.1@5.9,32.1 v2(5.9,33.1)
C_VP: F300.1 TP201.1 X1.2 | length 1
  Bottom Side w1.2: TP201.1@2.3,38.3 v2(2.3,39.3)
  other v1: 4.635,35.2 4.985,35.2 5.335,35.2 5.685,35.2 6.035,35.2 6.385,35.2 6.735,35.2 7.085,35.2 7.435,35.2 7.785,35.2 8.135,35.2 8.485,35.2 4.635,35.55 4.985,35.55 5.335,35.55 5.685,35.55 6.035,35.55 6.385,35.55 6.735,35.55 7.085,35.55 7.435,35.55 7.785,35.55 8.135,35.55 8.485,35.55 4.635,35.9 4.985,35.9 5.335,35.9 5.685,35.9 6.035,35.9 6.385,35.9 6.735,35.9 7.085,35.9 7.435,35.9 7.785,35.9 8.135,35.9 8.485,35.9 5.475,36.8 5.825,36.8 6.175,36.8 6.525,36.8 6.875,36.8 7.225,36.8 5.475,37.15 5.825,37.15 6.175,37.15 6.525,37.15 6.875,37.15 7.225,37.15 5.475,37.5 5.825,37.5 6.175,37.5 6.525,37.5 6.875,37.5 7.225,37.5 5.475,37.85 5.825,37.85 6.175,37.85 6.525,37.85 6.875,37.85 7.225,37.85 5.475,38.2 5.825,38.2 6.175,38.2 6.525,38.2 6.875,38.2 7.225,38.2 5.475,38.55 5.825,38.55 6.175,38.55 6.525,38.55 6.875,38.55 7.225,38.55 5.475,38.9 5.825,38.9 6.175,38.9 6.525,38.9 6.875,38.9 7.225,38.9 5.475,39.25 5.825,39.25 6.175,39.25 6.525,39.25 6.875,39.25 7.225,39.25 4.635,40.1 4.985,40.1 5.335,40.1 5.685,40.1 6.035,40.1 6.385,40.1 6.735,40.1 7.085,40.1 7.435,40.1 7.785,40.1 8.135,40.1 8.485,40.1 4.635,40.45 4.985,40.45 5.335,40.45 5.685,40.45 6.035,40.45 6.385,40.45 6.735,40.45 7.085,40.45 7.435,40.45 7.785,40.45 8.135,40.45 8.485,40.45 4.635,40.8 4.985,40.8 5.335,40.8 5.685,40.8 6.035,40.8 6.385,40.8 6.735,40.8 7.085,40.8 7.435,40.8 7.785,40.8 8.135,40.8 8.485,40.8
  other v2: 4.4,43.528 6.1,43.528 3.778,44.15 6.722,44.15 3.778,45.85 6.722,45.85 4.4,46.472 6.1,46.472
C_W1: C303.2 C306.2 L300.2 TP207.1 X3.1
  other v1: 54.45,35.55 54.8,35.55 55.15,35.55 55.5,35.55 55.85,35.55 56.2,35.55 56.55,35.55 56.9,35.55 57.25,35.55 54.45,35.9 54.8,35.9 55.15,35.9 55.5,35.9 55.85,35.9 56.2,35.9 56.55,35.9 56.9,35.9 57.25,35.9 54.45,36.25 54.8,36.25 55.15,36.25 55.5,36.25 55.85,36.25 56.2,36.25 56.55,36.25 56.9,36.25 57.25,36.25 54.45,36.6 54.8,36.6 55.15,36.6 55.5,36.6 55.85,36.6 56.2,36.6 56.55,36.6 56.9,36.6 57.25,36.6 54.45,36.95 54.8,36.95 55.15,36.95 55.5,36.95 55.85,36.95 56.2,36.95 56.55,36.95 56.9,36.95 57.25,36.95 54.45,37.3 54.8,37.3 55.15,37.3 55.5,37.3 55.85,37.3 56.2,37.3 56.55,37.3 56.9,37.3 57.25,37.3 54.45,37.65 54.8,37.65 55.15,37.65 55.5,37.65 55.85,37.65 56.2,37.65 56.55,37.65 56.9,37.65 57.25,37.65 54.45,38 54.8,38 55.15,38 55.5,38 55.85,38 56.2,38 56.55,38 56.9,38 57.25,38 54.45,38.35 54.8,38.35 55.15,38.35 55.5,38.35 55.85,38.35 56.2,38.35 56.55,38.35 56.9,38.35 57.25,38.35 54.45,38.7 54.8,38.7 55.15,38.7 55.5,38.7 55.85,38.7 56.2,38.7 56.55,38.7 56.9,38.7 57.25,38.7 54.45,39.05 54.8,39.05 55.15,39.05 55.5,39.05 55.85,39.05 56.2,39.05 56.55,39.05 56.9,39.05 57.25,39.05 54.45,39.4 54.8,39.4 55.15,39.4 55.5,39.4 55.85,39.4 56.2,39.4 56.55,39.4 56.9,39.4 57.25,39.4 54.45,39.75 54.8,39.75 55.15,39.75 55.5,39.75 55.85,39.75 56.2,39.75 56.55,39.75 56.9,39.75 57.25,39.75 54.45,40.1 54.8,40.1 55.15,40.1 55.5,40.1 55.85,40.1 56.2,40.1 56.55,40.1 56.9,40.1 57.25,40.1 54.45,40.45 54.8,40.45 55.15,40.45 55.5,40.45 55.85,40.45 56.2,40.45 56.55,40.45 56.9,40.45 57.25,40.45
  other v2: 64.625,28.728 66.625,28.728 64.003,29.35 67.247,29.35 64.003,31.35 67.247,31.35 64.625,31.972 66.625,31.972 60.05,36.525 60.7,36.525 60.05,37.175 60.7,37.175 60.05,37.825 60.7,37.825 60.05,38.475 60.7,38.475 60.05,39.125 60.7,39.125 60.05,39.775 60.7,39.775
